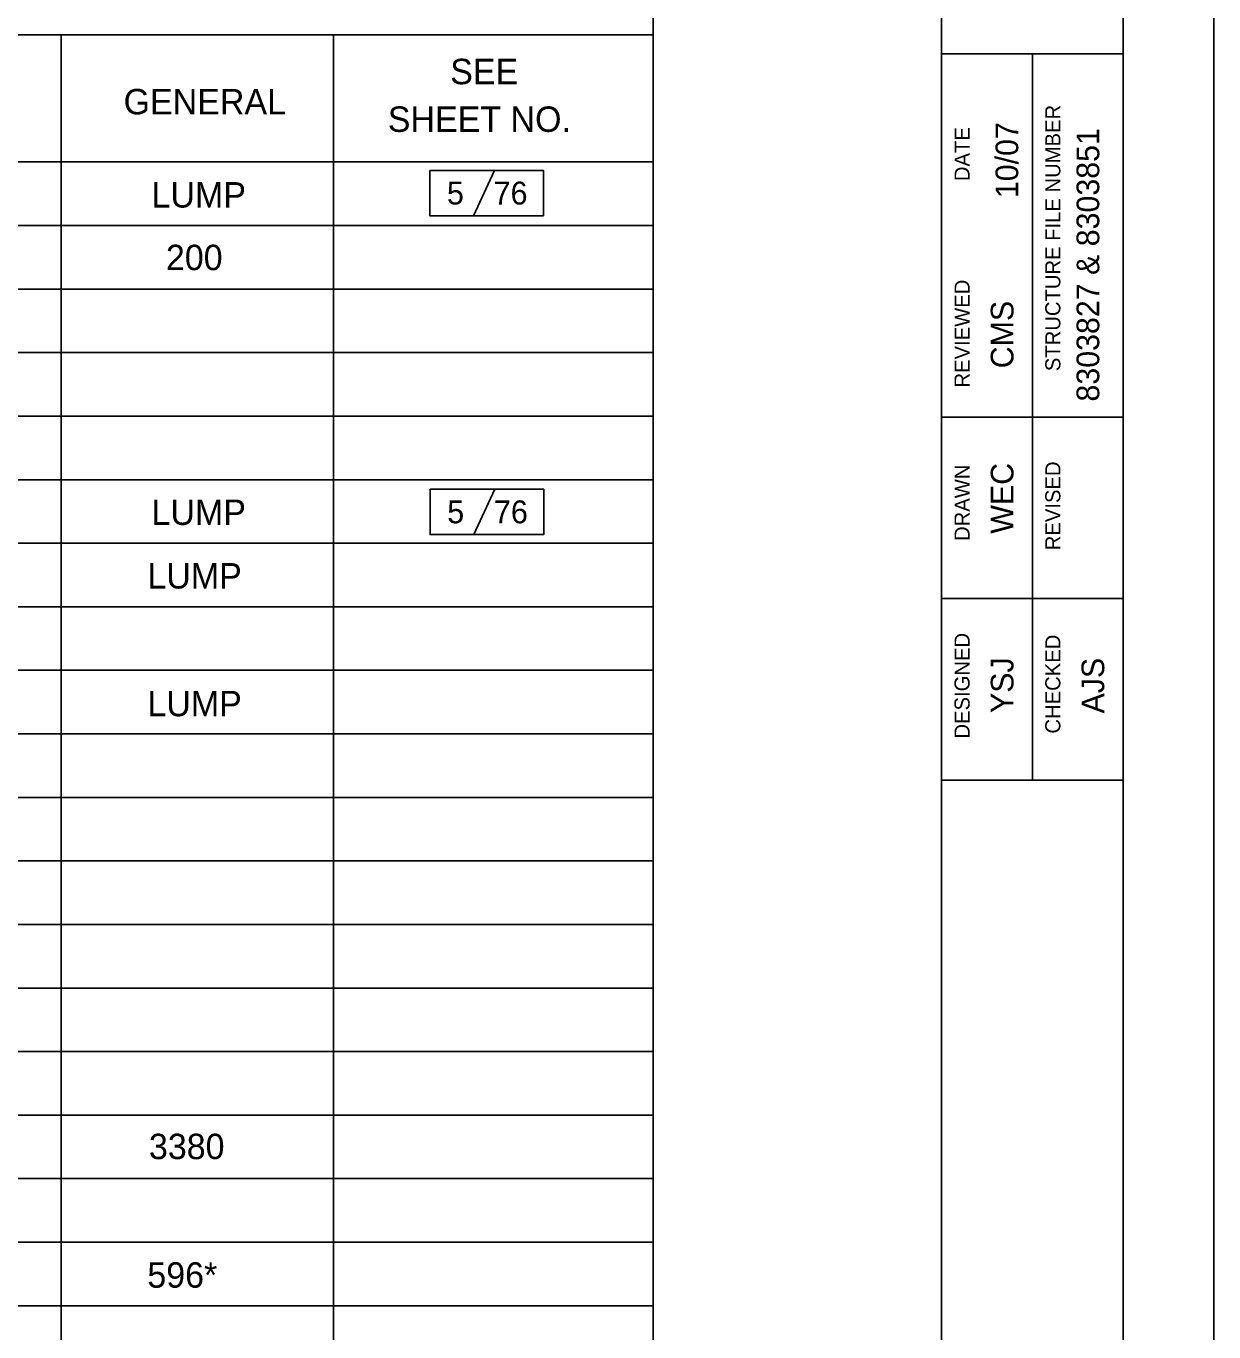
# Model space of a CAD drawing. Extents: x 0 to 34, y 0 to 22.
# Drawn here: x 27.46 to 34, y 10.96 to 18.15 of the extents above; entities that cross this region are included whole.
import ezdxf

# ---------------------------------------------------------------- set-up
doc = ezdxf.new("R2010")
doc.units = 0
for name, color, linetype in [('BR_P_Gen_Text', 7, 'Continuous'), ('SH_Border', 7, 'Continuous'), ('SH_Cut_Line', 7, 'Continuous'), ('SH_Data', 7, 'Continuous'), ('SH_Text', 7, 'Continuous')]:
    doc.layers.add(name, color=color, linetype=linetype)

msp = doc.modelspace()

# ---------------------------------------------------------------- linework, layer by layer
at = {"layer": 'BR_P_Gen_Text'}
for p, q in [((30.0366, 17.3587), (29.921, 17.1088)), ((30.0384, 15.6028), (29.9228, 15.3529))]:
    msp.add_line(p, q, dxfattribs=at)
for points in [[(29.6796, 17.3587), (30.3057, 17.3587), (30.3057, 17.1088), (29.6796, 17.1088)], [(29.6796, 17.3587), (30.3057, 17.3587), (30.3057, 17.1088), (29.6796, 17.1088)], [(29.6814, 15.6028), (30.3075, 15.6028), (30.3075, 15.3529), (29.6814, 15.3529)], [(29.6814, 15.6028), (30.3075, 15.6028), (30.3075, 15.3529), (29.6814, 15.3529)]]:
    msp.add_lwpolyline(points, close=True, dxfattribs=at)
at = {"layer": 'SH_Border'}
for p, q in [((32.5, 0.5), (32.5, 21.5)), ((32.5, 0.5), (32.5, 21.5)), ((32.5, 0.5), (32.5, 21.5)), ((32.5, 18), (33.5, 18)), ((32.5, 18), (33.5, 18)), ((32.5, 18), (33.5, 18)), ((33, 14), (33, 18)), ((33, 14), (33, 18)), ((33, 14), (33, 18)), ((32.5, 16), (33.5, 16)), ((32.5, 16), (33.5, 16)), ((32.5, 16), (33.5, 16)), ((32.5, 15), (33.5, 15)), ((32.5, 15), (33.5, 15)), ((32.5, 15), (33.5, 15)), ((32.5, 14), (33.5, 14)), ((32.5, 14), (33.5, 14)), ((32.5, 14), (33.5, 14))]:
    msp.add_line(p, q, dxfattribs=at)
msp.add_lwpolyline([(2, 21.5), (33.5, 21.5), (33.5, 0.5), (2, 0.5)], close=True, dxfattribs=at)
at = {"layer": 'SH_Cut_Line'}
msp.add_lwpolyline([(0, 22), (34, 22), (34, 0), (0, 0)], close=True, dxfattribs=at)
at = {"layer": 'SH_Text'}
for p, q in [((30.91, 19.0627), (30.91, 5.1552)), ((3.59, 18.1052), (30.91, 18.1052)), ((27.6498, 18.1052), (27.6498, 5.1552)), ((29.1498, 18.1052), (29.1498, 5.1552)), ((3.59, 17.4052), (30.91, 17.4052)), ((3.59, 17.0552), (30.91, 17.0552)), ((3.59, 16.7052), (30.91, 16.7052)), ((3.59, 16.3552), (30.91, 16.3552)), ((3.59, 16.0052), (30.91, 16.0052)), ((3.59, 15.6552), (30.91, 15.6552)), ((3.59, 15.3052), (30.91, 15.3052)), ((3.59, 14.9552), (30.91, 14.9552)), ((3.59, 14.6052), (30.91, 14.6052)), ((3.59, 14.2552), (30.91, 14.2552)), ((3.59, 13.9052), (30.91, 13.9052)), ((3.59, 13.5552), (30.91, 13.5552)), ((3.59, 13.2052), (30.91, 13.2052)), ((3.59, 12.8552), (30.91, 12.8552)), ((3.59, 12.5052), (30.91, 12.5052)), ((3.59, 12.1552), (30.91, 12.1552)), ((3.59, 11.8052), (30.91, 11.8052)), ((3.59, 11.4552), (30.91, 11.4552)), ((3.59, 11.1052), (30.91, 11.1052))]:
    msp.add_line(p, q, dxfattribs=at)

# ---------------------------------------------------------------- texts
at = {"layer": 'BR_P_Gen_Text'}
for s, p in [(' 5', (29.7275, 17.1708)), ('76', (30.0314, 17.1708)), (' 5', (29.7292, 15.4149)), ('76', (30.0332, 15.4149))]:
    msp.add_text(s, height=0.12587, dxfattribs=at).set_placement(p)
at = {"layer": 'SH_Data'}
for s, height, p in [('STRUCTURE FILE NUMBER', 0.0833, (33.1542, 16.253)), ('DATE', 0.0833, (32.6542, 17.2997)), ('10/07', 0.125, (32.9221, 17.206)), ('8303827 & 8303851', 0.125, (33.3684, 16.0856)), ('REVIEWED', 0.0833, (32.6542, 16.1627)), ('CMS', 0.125, (32.8958, 16.2687)), ('DRAWN', 0.0833, (32.6542, 15.3177)), ('WEC', 0.125, (32.8958, 15.3576)), ('REVISED', 0.0833, (33.1542, 15.2665)), ('DESIGNED', 0.0833, (32.6542, 14.2292)), ('CHECKED', 0.0833, (33.1542, 14.2567)), ('YSJ', 0.125, (32.8958, 14.3699)), ('AJS', 0.125, (33.3958, 14.3675))]:
    msp.add_text(s, height=height, rotation=90, dxfattribs=at).set_placement(p)
at = {"layer": 'SH_Text'}
for s, p in [('SEE', (29.7925, 17.8334)), ('GENERAL', (27.993, 17.6674)), ('SHEET NO.', (29.4486, 17.5709)), ('LUMP', (28.1468, 17.1541)), ('200', (28.2261, 16.8092)), ('LUMP', (28.1468, 15.4057)), ('LUMP', (28.1242, 15.0557)), ('LUMP', (28.1242, 14.3521)), ('3380', (28.1326, 11.9126)), ('596*', (28.1238, 11.2046))]:
    msp.add_text(s, height=0.14, dxfattribs=at).set_placement(p)

doc.saveas('drawing.dxf')
